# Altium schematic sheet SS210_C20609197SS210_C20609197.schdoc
size 127 x 101 mm
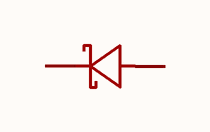
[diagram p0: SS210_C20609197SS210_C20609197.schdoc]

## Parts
D?  ss210_c20609197  [SMA_L4.3-W2.5-LS5.0-RD]  (value not drawn)

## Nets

Not connected (* = marked no-connect by the designer): D? 1(C) 2(A)

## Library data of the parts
D? = ss210_c20609197: 二极管配置:1个独立式;正向压降(Vf):850mV@2A;直流反向耐压(Vr):100V;整流电流:2A;; Manufacturer: JSMSEMI(杰盛微); ManufacturerPart: SS210; AddInBom: yes; ModelId: 5b53cc1b87a148cc9fa13125be89f948; ModelTransform: 194.8815,98.425,0,0,0,0,0,0,0; Diode Configuration: 1个独立式; Voltage - DC Reverse(Vr): 100V; Current - Rectified: 2A; Reverse Leakage Current (Ir): 500uA@100V; Operating Junction Temperature Range: -55℃~+150℃; Non-Repetitive Peak Forward Surge Current: 50A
